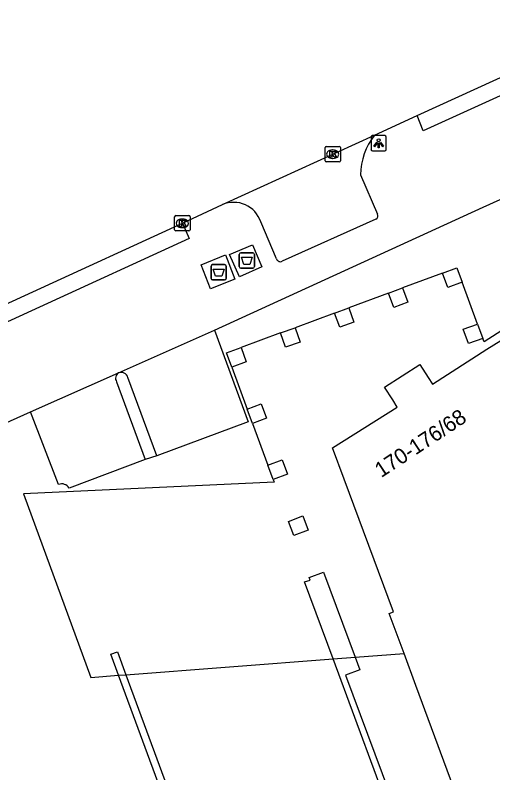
# Model space of a CAD drawing. Extents: x 160806 to 161707, y 383697 to 384148.
# Drawn here: x 161003.06 to 161034.17, y 383957.35 to 384006.74 of the extents above; entities that cross this region are included whole.
import ezdxf

# ---------------------------------------------------------------- set-up
doc = ezdxf.new("R2010")
doc.units = 0
for name, color, linetype in [('IMGEO_Afval_apart_plaats', 7, 'Continuous'), ('IMGEO_Kolk', 7, 'Continuous'), ('IMGEO_Lichtpunt', 7, 'Continuous'), ('IMGEO_Muur', 7, 'Continuous'), ('IMGEO_Pand', 7, 'Continuous'), ('IMGEO_Pand_nummerreeks', 7, 'Continuous'), ('IMGEO_Pand_overbouw', 7, 'Continuous'), ('IMGEO_Rijbaan_lokaal_open', 7, 'Continuous'), ('IMGEO_Verkeerseiland_open', 7, 'Continuous'), ('IMGEO_Voetpad_gesloten', 7, 'Continuous'), ('IMGEO_Voetpad_open', 7, 'Continuous')]:
    doc.layers.add(name, color=color, linetype=linetype)

msp = doc.modelspace()

# ---------------------------------------------------------------- linework, layer by layer
at = {"layer": 'IMGEO_Afval_apart_plaats'}
for p, q in [((161017.752, 383991.248), (161018.542, 383991.248)), ((161018.542, 383991.248), (161017.752, 383991.248)), ((161017.652, 383990.348), (161017.652, 383991.148)), ((161017.652, 383991.148), (161017.652, 383990.348)), ((161018.642, 383991.148), (161018.642, 383990.348)), ((161018.642, 383990.348), (161018.642, 383991.148)), ((161015.814, 383989.58), (161015.814, 383990.38)), ((161015.814, 383990.38), (161015.814, 383989.58)), ((161015.914, 383990.48), (161016.704, 383990.48)), ((161016.704, 383990.48), (161015.914, 383990.48)), ((161016.804, 383990.38), (161016.804, 383989.58)), ((161016.804, 383989.58), (161016.804, 383990.38)), ((161018.542, 383990.248), (161017.752, 383990.248)), ((161017.752, 383990.248), (161018.542, 383990.248)), ((161016.704, 383989.48), (161015.914, 383989.48)), ((161015.914, 383989.48), (161016.704, 383989.48))]:
    msp.add_line(p, q, dxfattribs=at)
for points in [[(161017.795, 383990.962), (161018.499, 383990.962), (161018.35, 383990.492), (161017.944, 383990.492), (161017.795, 383990.962)], [(161015.957, 383990.194), (161016.661, 383990.194), (161016.512, 383989.724), (161016.106, 383989.724), (161015.957, 383990.194)]]:
    msp.add_lwpolyline(points, dxfattribs=at)
for centre, start, end in [((161017.752, 383991.148), 90, 180), ((161017.752, 383991.148), 90, 180), ((161018.542, 383991.148), 0, 90), ((161018.542, 383991.148), 360, 90), ((161015.914, 383990.38), 90, 180), ((161015.914, 383990.38), 90, 180), ((161016.704, 383990.38), 0, 90), ((161016.704, 383990.38), 360, 90), ((161017.752, 383990.348), 180, 270), ((161017.752, 383990.348), 180, 270), ((161018.542, 383990.348), 270, 0), ((161018.542, 383990.348), 270, 0), ((161015.914, 383989.58), 180, 270), ((161015.914, 383989.58), 180, 270), ((161016.704, 383989.58), 270, 0), ((161016.704, 383989.58), 270, 0)]:
    msp.add_arc(centre, 0.1, start, end, dxfattribs=at)
at = {"layer": 'IMGEO_Kolk'}
for p, q in [((161023.315, 383998.182), (161024.167, 383998.182)), ((161023.24, 383997.256), (161023.24, 383998.108)), ((161023.728, 383997.962), (161023.753, 383997.962)), ((161024.241, 383998.108), (161024.241, 383997.256)), ((161024.167, 383997.182), (161023.315, 383997.182)), ((161023.751, 383997.402), (161023.726, 383997.402)), ((161013.446, 383992.748), (161013.446, 383993.6)), ((161013.521, 383993.674), (161014.373, 383993.674)), ((161013.934, 383993.454), (161013.959, 383993.454)), ((161014.447, 383993.6), (161014.447, 383992.748)), ((161013.957, 383992.894), (161013.932, 383992.894)), ((161014.373, 383992.674), (161013.521, 383992.674))]:
    msp.add_line(p, q, dxfattribs=at)
for points in [[(161023.315, 383998.182), (161024.167, 383998.182)], [(161023.24, 383997.256), (161023.24, 383998.108)], [(161023.561, 383997.882), (161023.684, 383997.882), (161023.684, 383997.731), (161023.814, 383997.882), (161023.978, 383997.882), (161023.832, 383997.731), (161023.985, 383997.482), (161023.833, 383997.482), (161023.748, 383997.646), (161023.684, 383997.579), (161023.684, 383997.482), (161023.561, 383997.482), (161023.561, 383997.882)], [(161024.241, 383998.108), (161024.241, 383997.256)], [(161024.167, 383997.182), (161023.315, 383997.182)], [(161013.446, 383992.748), (161013.446, 383993.6)], [(161013.521, 383993.674), (161014.373, 383993.674)], [(161013.767, 383993.374), (161013.89, 383993.374), (161013.89, 383993.223), (161014.02, 383993.374), (161014.184, 383993.374), (161014.038, 383993.223), (161014.191, 383992.974), (161014.039, 383992.974), (161013.954, 383993.138), (161013.89, 383993.071), (161013.89, 383992.974), (161013.767, 383992.974), (161013.767, 383993.374)], [(161014.447, 383993.6), (161014.447, 383992.748)], [(161014.373, 383992.674), (161013.521, 383992.674)]]:
    msp.add_lwpolyline(points, dxfattribs=at)
for centre, start, end in [((161023.317, 383998.106), 91.552, 178.448), ((161023.317, 383998.106), 91.552, 178.448), ((161024.165, 383998.106), 1.552, 88.448), ((161024.165, 383998.106), 1.552, 88.448), ((161023.317, 383997.258), 181.552, 268.448), ((161023.317, 383997.258), 181.552, 268.448), ((161024.165, 383997.258), 271.552, 358.448), ((161024.165, 383997.258), 271.552, 358.448), ((161013.523, 383993.598), 91.552, 178.448), ((161013.523, 383993.598), 91.552, 178.448), ((161014.371, 383993.598), 1.552, 88.448), ((161014.371, 383993.598), 1.552, 88.448), ((161013.523, 383992.75), 181.552, 268.448), ((161013.523, 383992.75), 181.552, 268.448), ((161014.371, 383992.75), 271.552, 358.448), ((161014.371, 383992.75), 271.552, 358.448)]:
    msp.add_arc(centre, 0.0765, start, end, dxfattribs=at)
for centre, major_axis, ratio, start_param, end_param in [((161023.727, 383997.682), (-0.387, 0.002), 0.722429, 4.712389, 7.853982), ((161023.752, 383997.682), (-0.39, 0.002), 0.717154, 1.570796, 4.712389), ((161013.933, 383993.174), (-0.387, 0.002), 0.722429, 4.712389, 7.853982), ((161013.958, 383993.174), (-0.39, 0.002), 0.717154, 1.570796, 4.712389)]:
    msp.add_ellipse(centre, major_axis=major_axis, ratio=ratio, start_param=start_param, end_param=end_param, dxfattribs=at)
at = {"layer": 'IMGEO_Lichtpunt'}
for p, q in [((161026.237, 383998.794), (161026.237, 383997.987)), ((161026.237, 383998.794), (161026.237, 383997.987)), ((161027.139, 383998.889), (161026.331, 383998.889)), ((161027.139, 383998.889), (161026.331, 383998.889)), ((161027.233, 383997.987), (161027.233, 383998.794)), ((161027.233, 383997.987), (161027.233, 383998.794)), ((161026.331, 383997.893), (161027.139, 383997.893)), ((161026.331, 383997.893), (161027.139, 383997.893))]:
    msp.add_line(p, q, dxfattribs=at)
for points in [[(161026.611, 383998.458), (161026.65, 383998.43), (161026.462, 383998.168), (161026.424, 383998.195), (161026.611, 383998.458)], [(161026.713, 383998.41), (161026.76, 383998.41), (161026.76, 383998.088), (161026.713, 383998.088), (161026.713, 383998.41)], [(161026.823, 383998.43), (161026.861, 383998.457), (161027.048, 383998.195), (161027.009, 383998.167), (161026.823, 383998.43)]]:
    msp.add_lwpolyline(points, dxfattribs=at)
msp.add_circle((161026.736, 383998.592), 0.0994, dxfattribs=at)
for centre, start, end in [((161026.331, 383998.794), 90, 180), ((161026.331, 383998.794), 90, 180), ((161027.139, 383998.794), 0, 90), ((161027.139, 383998.794), 0, 90), ((161026.331, 383997.987), 180, 270), ((161026.331, 383997.987), 180, 270), ((161027.139, 383997.987), 270, 0), ((161027.139, 383997.987), 270, 360)]:
    msp.add_arc(centre, 0.0946, start, end, dxfattribs=at)
at = {"layer": 'IMGEO_Muur'}
for points in [[(161028.006, 383953.311), (161023.769, 383964.777), (161021.913, 383969.799), (161022.283, 383969.906), (161022.217, 383970.084), (161023.149, 383970.43), (161025.209, 383964.887), (161025.517, 383964.059), (161024.585, 383963.712), (161028.394, 383953.457)], [(161015.359, 383948.563), (161009.799, 383963.711), (161009.295, 383965.084), (161009.724, 383965.245), (161010.275, 383963.748), (161015.805, 383948.731)]]:
    msp.add_lwpolyline(points, dxfattribs=at)
at = {"layer": 'IMGEO_Pand'}
for points in [[(161030.891, 383989.918), (161031.826, 383990.262), (161032.167, 383989.335), (161031.232, 383988.991), (161030.891, 383989.918)], [(161027.368, 383988.622), (161028.291, 383988.972), (161028.644, 383988.044), (161027.721, 383987.693), (161027.368, 383988.622)], [(161023.863, 383987.325), (161024.788, 383987.658), (161025.123, 383986.728), (161024.198, 383986.395), (161023.863, 383987.325)], [(161020.35, 383986.041), (161021.288, 383986.369), (161021.615, 383985.433), (161020.676, 383985.105), (161020.35, 383986.041)], [(161032.588, 383985.337), (161032.248, 383986.269), (161033.175, 383986.607), (161033.515, 383985.675), (161032.588, 383985.337)], [(161036.521, 383943.129), (161029.163, 383963.05), (161028.394, 383965.13), (161027.43, 383967.74), (161027.703, 383967.834), (161024.49, 383976.502), (161023.739, 383978.541), (161027.95, 383981.197), (161027.654, 383981.66), (161027.121, 383982.495), (161029.428, 383983.968), (161029.967, 383983.13), (161030.253, 383982.685), (161033.788, 383984.963), (161035.788, 383986.213), (161039.555, 383976.079), (161040.298, 383976.355), (161041.681, 383972.596), (161042.034, 383971.666), (161049.712, 383950.913), (161049.393, 383950.795), (161050.333, 383948.273), (161036.521, 383943.129)], [(161017.167, 383983.795), (161016.831, 383984.729), (161017.772, 383985.068), (161018.108, 383984.135), (161017.167, 383983.795)], [(161018.516, 383980.127), (161018.163, 383981.062), (161019.086, 383981.412), (161019.44, 383980.477), (161018.516, 383980.127)], [(161019.868, 383976.465), (161019.521, 383977.399), (161020.45, 383977.744), (161020.797, 383976.81), (161019.868, 383976.465)], [(161021.22, 383972.811), (161020.86, 383973.741), (161021.786, 383974.099), (161022.146, 383973.169), (161021.22, 383972.811)]]:
    msp.add_lwpolyline(points, dxfattribs=at)
at = {"layer": 'IMGEO_Pand_overbouw'}
msp.add_lwpolyline([(161036.149, 383987.067), (161033.602, 383985.445), (161033.515, 383985.675), (161032.588, 383985.337), (161032.248, 383986.269), (161033.175, 383986.607), (161032.167, 383989.335), (161031.232, 383988.991), (161030.891, 383989.918), (161028.291, 383988.972), (161028.644, 383988.044), (161027.721, 383987.693), (161027.368, 383988.622), (161024.788, 383987.658), (161025.123, 383986.728), (161024.198, 383986.395), (161023.863, 383987.325), (161021.288, 383986.369), (161021.615, 383985.433), (161020.676, 383985.105), (161020.35, 383986.041), (161017.772, 383985.068), (161018.108, 383984.135), (161017.167, 383983.795), (161018.163, 383981.062), (161019.086, 383981.412), (161019.44, 383980.477), (161018.516, 383980.127), (161019.521, 383977.399), (161020.45, 383977.744), (161020.797, 383976.81), (161019.868, 383976.465), (161019.933, 383976.289), (161003.595, 383975.527), (161007.986, 383963.573), (161009.799, 383963.711), (161010.275, 383963.748), (161023.769, 383964.777), (161025.209, 383964.887), (161028.394, 383965.13), (161027.43, 383967.74), (161027.703, 383967.834), (161024.49, 383976.502), (161023.739, 383978.541), (161027.95, 383981.197), (161027.654, 383981.66), (161027.121, 383982.495), (161029.428, 383983.968), (161029.967, 383983.13), (161030.253, 383982.685), (161033.788, 383984.963), (161035.788, 383986.213)], dxfattribs=at)
at = {"layer": 'IMGEO_Rijbaan_lokaal_open'}
for points in [[(161029.244, 384000.203), (161043.571, 384006.745)], [(161026.469, 383998.931), (161029.244, 384000.203)], [(161016.563, 383994.396), (161026.469, 383998.931)], [(161013.947, 383993.174), (161016.563, 383994.396)], [(160994.436, 383984.241), (161013.947, 383993.174)]]:
    msp.add_lwpolyline(points, dxfattribs=at)
at = {"layer": 'IMGEO_Verkeerseiland_open'}
msp.add_lwpolyline([(161012.287, 383978.018), (161011.521, 383977.773)], dxfattribs=at)
at = {"layer": 'IMGEO_Voetpad_gesloten'}
for points in [[(161017.024, 383991.147), (161018.511, 383991.768), (161019.116, 383990.339), (161017.662, 383989.69), (161017.024, 383991.147)], [(161015.184, 383990.472), (161016.749, 383991.111), (161017.358, 383989.531), (161015.79, 383988.906), (161015.184, 383990.472)]]:
    msp.add_lwpolyline(points, dxfattribs=at)
at = {"layer": 'IMGEO_Voetpad_open'}
for points in [[(161043.571, 384006.745), (161044.013, 384005.753), (161029.634, 383999.203), (161029.244, 384000.203)], [(161016.05, 383986.21), (161033.55, 383994.222), (161042.251, 383998.166)], [(161025.542, 383996.328), (161026.665, 383993.775)], [(161020.078, 383990.854), (161019.055, 383993.28)], [(161026.55, 383993.448), (161020.453, 383990.696)], [(161013.947, 383993.174), (161014.397, 383992.177), (160994.873, 383983.238), (160994.436, 383984.241)], [(161009.792, 383983.427), (161016.05, 383986.21)], [(161016.05, 383986.21), (161018.24, 383980.237), (161012.287, 383978.018)], [(161004.053, 383980.875), (161009.792, 383983.427)], [(161009.667, 383982.847), (161011.521, 383977.773)], [(161012.287, 383978.018), (161010.404, 383983.129)], [(160998.353, 383977.077), (160997.944, 383978.148), (161004.053, 383980.875)], [(161005.888, 383976.146), (161004.053, 383980.875)], [(161011.521, 383977.773), (161006.566, 383975.908)]]:
    msp.add_lwpolyline(points, dxfattribs=at)
for centre, radius, start, end in [((161030.004, 383996.206), 4.464, 142.3677, 178.4278), ((161017.287, 383992.673), 1.869, 18.9437, 112.8075), ((161026.443, 383993.669), 0.246, 295.8028, 25.4455), ((161020.34, 383990.951), 0.279, 200.3554, 293.95), ((161010.005, 383983.078), 0.409, 121.3575, 214.3181), ((161009.954, 383982.982), 0.473, 18.0396, 110.0348), ((161006.093, 383975.646), 0.541, 29.0166, 112.2979)]:
    msp.add_arc(centre, radius, start, end, dxfattribs=at)

# ---------------------------------------------------------------- texts
at = {"layer": 'IMGEO_Pand_nummerreeks'}
msp.add_text('170-176/68', height=1, rotation=33.513, dxfattribs=at).set_placement((161026.906, 383976.559))

doc.saveas('drawing.dxf')
